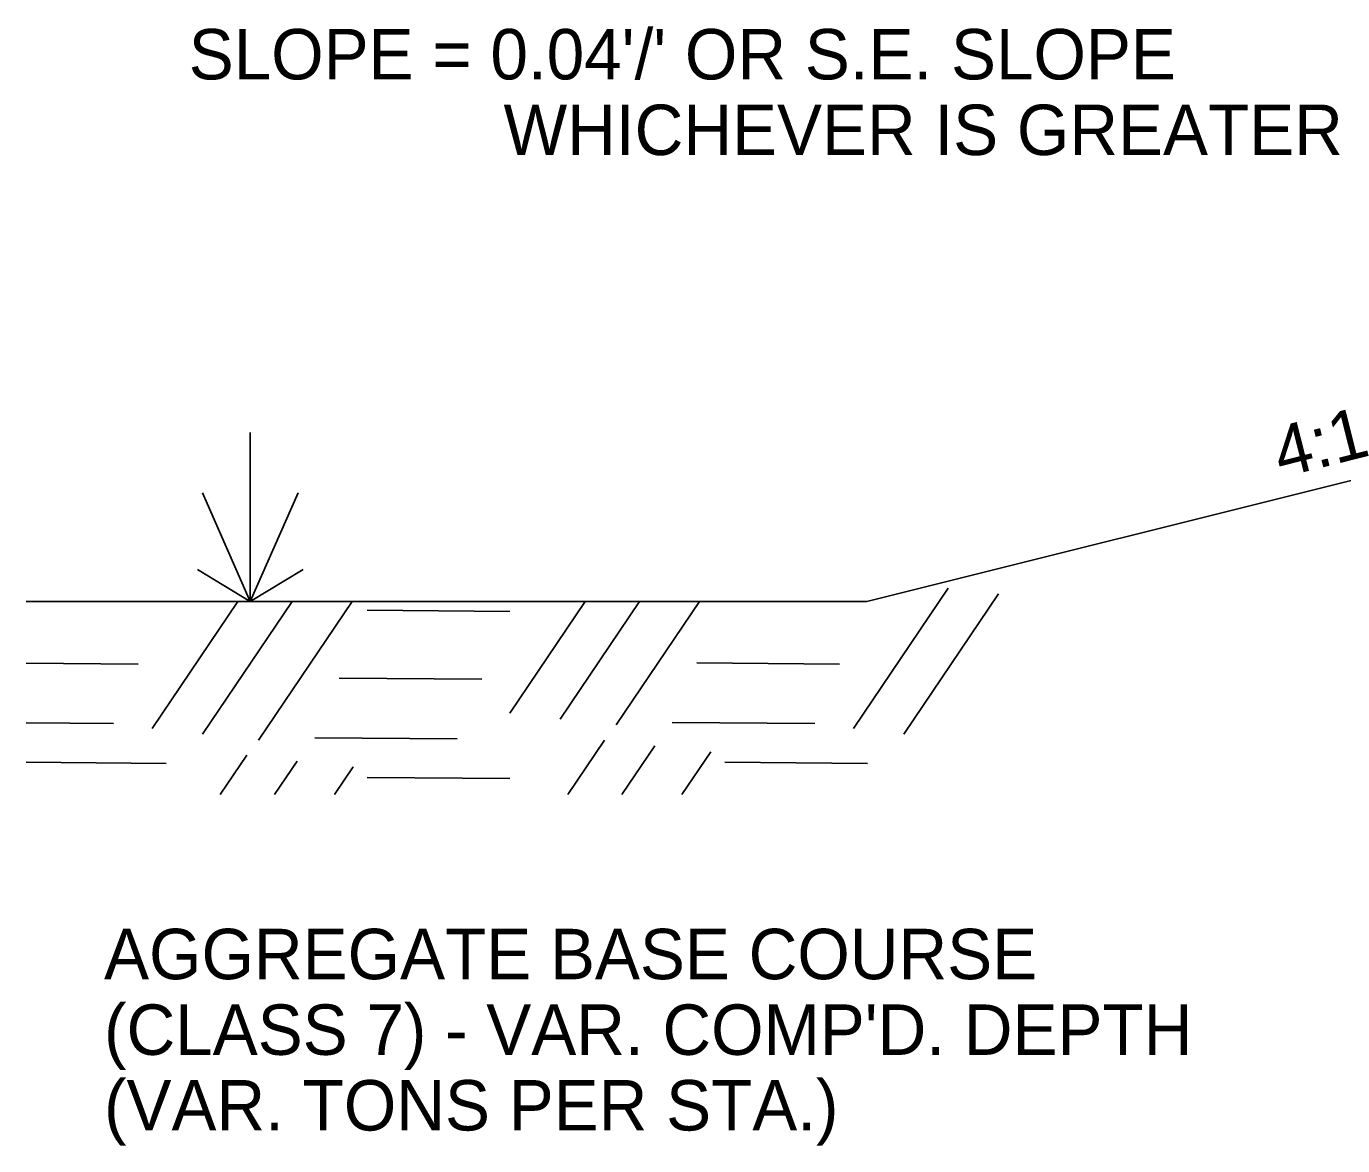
# Model space of a CAD drawing. Extents: x 1955768 to 1955917, y 566446 to 566546.
# Drawn here: x 1955802.53 to 1955818.19, y 566455.88 to 566469.2 of the extents above; entities that cross this region are included whole.
import ezdxf

# ---------------------------------------------------------------- set-up
doc = ezdxf.new("R2010")
doc.units = 0
for name, color, linetype in [('R_Border', 7, 'Continuous'), ('R_Grid', 7, 'Continuous'), ('R_Logo', 7, 'Continuous')]:
    doc.layers.add(name, color=color, linetype=linetype)

msp = doc.modelspace()

# ---------------------------------------------------------------- linework, layer by layer
at = {"layer": 'R_Border'}
for q in [(1955826.173, 566465.764), (1955802.527, 566462.353)]:
    msp.add_line((1955812.527, 566462.353), q, dxfattribs=at)
at = {"layer": 'R_Grid'}
for p, q in [((1955812.368, 566460.842), (1955813.494, 566462.511)), ((1955812.966, 566460.773), (1955814.092, 566462.442)), ((1955804.025, 566460.842), (1955805.044, 566462.353)), ((1955804.623, 566460.773), (1955805.689, 566462.353)), ((1955805.29, 566460.703), (1955806.403, 566462.353)), ((1955808.28, 566461.023), (1955809.177, 566462.353)), ((1955808.878, 566460.953), (1955809.822, 566462.353)), ((1955809.545, 566460.884), (1955810.536, 566462.353)), ((1955806.583, 566462.247), (1955808.28, 566462.233)), ((1955802.527, 566461.618), (1955803.858, 566461.607)), ((1955810.505, 566461.621), (1955812.201, 566461.607)), ((1955806.25, 566461.44), (1955807.946, 566461.426)), ((1955802.527, 566460.906), (1955803.566, 566460.898)), ((1955810.213, 566460.912), (1955811.909, 566460.898)), ((1955805.958, 566460.731), (1955807.654, 566460.717)), ((1955808.968, 566460.054), (1955809.406, 566460.703)), ((1955809.613, 566460.054), (1955810.004, 566460.633)), ((1955810.328, 566460.054), (1955810.672, 566460.564)), ((1955802.527, 566460.438), (1955804.192, 566460.425)), ((1955804.835, 566460.054), (1955805.151, 566460.522)), ((1955805.48, 566460.054), (1955805.749, 566460.453)), ((1955806.195, 566460.054), (1955806.417, 566460.383)), ((1955810.838, 566460.439), (1955812.535, 566460.425)), ((1955806.583, 566460.258), (1955808.28, 566460.244))]:
    msp.add_line(p, q, dxfattribs=at)
at = {"layer": 'R_Logo'}
for q in [(1955805.192, 566464.361), (1955804.622, 566463.645), (1955805.761, 566463.645), (1955804.563, 566462.732), (1955805.821, 566462.732)]:
    msp.add_line((1955805.192, 566462.353), q, dxfattribs=at)

# ---------------------------------------------------------------- texts
at = {"layer": 'R_Border'}
for s, p in [("SLOPE = 0.04'/' OR S.E. SLOPE", (1955804.459, 566468.564)), ('WHICHEVER IS GREATER', (1955808.205, 566467.664)), ('AGGREGATE BASE COURSE', (1955803.452, 566457.857)), ("(CLASS 7) - VAR. COMP'D. DEPTH", (1955803.452, 566456.957)), ('(VAR. TONS PER STA.)', (1955803.452, 566456.057))]:
    msp.add_text(s, height=0.6, dxfattribs=at).set_placement(p)
msp.add_text('4:1', height=0.6, rotation=14.1451, dxfattribs=at).set_placement((1955817.454, 566463.822))

doc.saveas('drawing.dxf')
